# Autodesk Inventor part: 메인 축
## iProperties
Created: 2013-12
Part Number: 메인 축
Material: Steel
Document SubType Name: Modeling
Designer: 한국산업디자인학원
Categories: <?xml version="1.0" encoding="UTF-16"?> <MemberInstance><Categories><FamilyTemplate><FamilyTemplateParameter ValueType="xs:double" Id="1" ObjectReferenceKey="da
Density: 1 g/cm^3
CustomPartVersion: 1
Author: 한국산업디자인학원
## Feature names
1. Extrusion1
